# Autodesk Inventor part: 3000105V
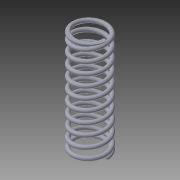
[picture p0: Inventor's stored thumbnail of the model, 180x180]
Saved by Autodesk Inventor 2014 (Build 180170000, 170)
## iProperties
Company: NHTSA/VRTC
Created: 2012-08
Material: Steel, Carbon
Document SubType Name: Modeling
Designer: Mike Vanvoorhis
Density: 7.87 g/cm^3
Description: MUSIC WIRE PRECISION COMPRESSION SPRING, ZINC-PLATED, 1.75" LGTH., .60" OD, .067" WIRE
Project: CHILD SIDE IMPACT SLED
Vendor: McMaster Carr
Stock Number: 9434K133
Part Number: 3000105V
Appearance: Semi-Polished
Translation Standard: IGES 5.3
FileName: C:\SW Working Folder\Fixes\9434K133.igs
PreProcessor: SolidWorks 2005 by SolidWorks Corporation
PostProcessor: Build: 160, Release: 2012 RTM - Date: Tue 03/01/2011
Sent Units: inch
Uncertainty: 1e-08
Author: Dave Walker
Title: Anti-Rebound Fixture Spring
Subject: Child Side Impact Sled
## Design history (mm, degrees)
node "9434K133.IGS1"
feature "Composite1"
body "Srf1"
